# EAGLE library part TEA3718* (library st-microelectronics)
STEPPER MOTOR DRIVER
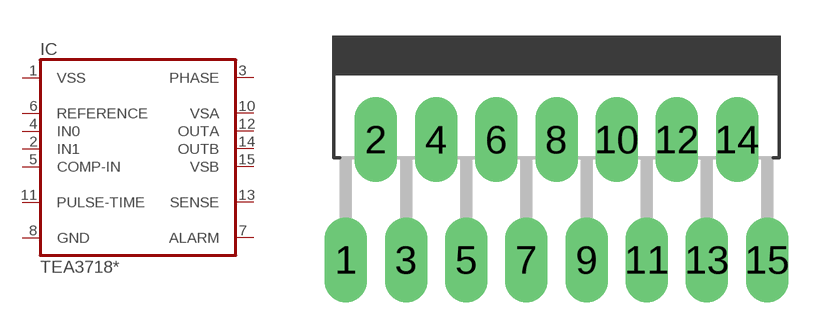
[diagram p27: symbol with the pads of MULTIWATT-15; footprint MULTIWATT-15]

Designator prefix IC

## TEA3718SP (MPN: E-TEA3718SP; OC_FARNELL: unknown; OC_NEWARK: 37M2588)  [MULTIWATT-15]
1  VSS  pwr
2  IN1  in
3  PHASE  in
4  IN0  in
5  COMP-IN  in
6  REFERENCE  in
7  ALARM  oc
8  GND  pwr
10  VSA  pwr
11  PULSE-TIME  pas
12  OUTA  out
13  SENSE  in
14  OUTB  out
15  VSB  pwr

## Footprint MULTIWATT-15 (pad centres in mm)
Multiwatt 15 lead
drill 1.2 long: 1 -8.89,-7.62; 2 -7.62,-2.54; 3 -6.35,-7.62; 4 -5.08,-2.54; 5 -3.81,-7.62; 6 -2.54,-2.54; 7 -1.27,-7.62; 8 0,-2.54; 9 1.27,-7.62; 10 2.54,-2.54; 11 3.81,-7.62; 12 5.08,-2.54; 13 6.35,-7.62; 14 7.62,-2.54; 15 8.89,-7.62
